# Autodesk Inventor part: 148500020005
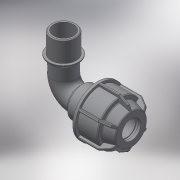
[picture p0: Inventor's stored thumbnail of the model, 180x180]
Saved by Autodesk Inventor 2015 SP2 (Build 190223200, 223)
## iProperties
Created: 2017-08
Part Number: 148500020005
Material: Generic
Description: PLASSON L.14 90° ELBOW MALE ADAPTOR (SILVER) 20-1/2"
Document SubType Name: Modeling
Designer: KIM
Density: 1 g/cm^3
Appearance: Default
Author: KIM
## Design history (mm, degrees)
derived "148500.ipt"
feature "Solid1::148500.ipt"
feature "Solid2::148500.ipt"
tag "TaggingFeature1"
body "Solid1"
body "Solid2"
other parameters: "d2" = 43, "d4" = 15 deg, "d5" = 28.38, "d6" = 9.3654, "d10" = 42, "d16" = 20.4, "d17" = 2.15, "d22" = 32, "d24" = 2.15, "d25" = 37.8, "d26" = 31.5, "d27" = 2.15, "d28" = 135 deg, "d29" = 1.29, "d31" = 1, "d46" = 150 deg, "d49" = 2.1, "d50" = 0, "d58" = 0.6, "d61" = 360 deg, "d63" = 18, "d94" = 44, "d96" = 23.0505, "d97" = 17, "d98" = 16.764, "d99" = 19.59292, "d100" = 135 deg, "d108" = 1, "d112" = 22.1, "d113" = 57, "d114" = 43.86, "d115" = 19.59292, "d116" = 45 deg, "d117" = 0, "d118" = 0, "d119" = 20.955, "d120" = 17, "d121" = 25.146, "d122" = 17.85, "d123" = 1, "R_" = 20.955, "E_" = 42, "A_" = 57, "l_" = 43, "l_2" = 17, "A_1" = 44
